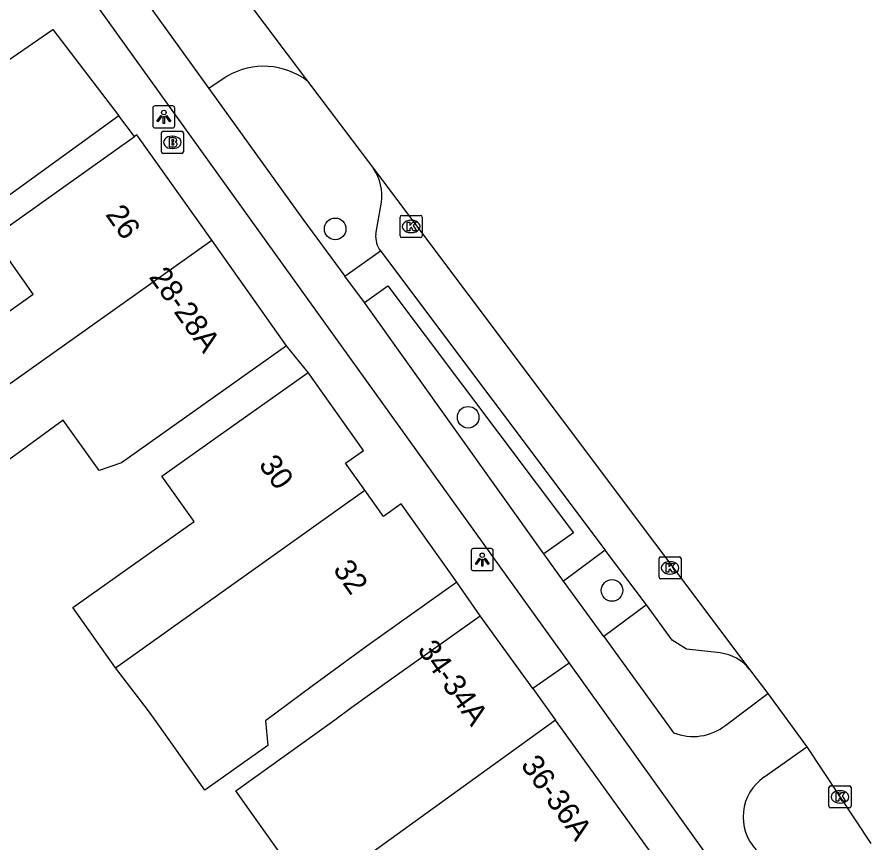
# Model space of a CAD drawing. Extents: x 161845 to 162341, y 381620 to 382158.
# Drawn here: x 162004.73 to 162043.44, y 382005.06 to 382042.47 of the extents above; entities that cross this region are included whole.
import ezdxf

# ---------------------------------------------------------------- set-up
doc = ezdxf.new("R2010")
doc.units = 0
for name, color, linetype in [('IMGEO_Boom', 7, 'Continuous'), ('IMGEO_Brandkraan', 7, 'Continuous'), ('IMGEO_Kolk', 7, 'Continuous'), ('IMGEO_Lichtpunt', 7, 'Continuous'), ('IMGEO_Pand', 7, 'Continuous'), ('IMGEO_Pand_nummerreeks', 7, 'Continuous'), ('IMGEO_Parkeervlak_open', 7, 'Continuous'), ('IMGEO_Rijbaan_lokaal_gesloten', 7, 'Continuous'), ('IMGEO_Rijbaan_lokaal_open', 7, 'Continuous'), ('IMGEO_Verkeerseiland_groen', 7, 'Continuous'), ('IMGEO_Voetpad_open', 7, 'Continuous')]:
    doc.layers.add(name, color=color, linetype=linetype)

msp = doc.modelspace()

# ---------------------------------------------------------------- linework, layer by layer
at = {"layer": 'IMGEO_Boom'}
for centre in [(162019.153, 382032.878), (162025.181, 382024.342), (162031.701, 382016.495)]:
    msp.add_circle(centre, 0.489, dxfattribs=at)
at = {"layer": 'IMGEO_Brandkraan'}
for p, q in [((162011.274, 382036.372), (162011.274, 382037.224)), ((162011.349, 382037.298), (162012.201, 382037.298)), ((162011.762, 382037.078), (162011.787, 382037.078)), ((162012.275, 382037.224), (162012.275, 382036.372)), ((162012.201, 382036.298), (162011.349, 382036.298)), ((162011.785, 382036.518), (162011.76, 382036.518))]:
    msp.add_line(p, q, dxfattribs=at)
for points in [[(162011.274, 382036.372), (162011.274, 382037.224)], [(162011.349, 382037.298), (162012.201, 382037.298)], [(162012.275, 382037.224), (162012.275, 382036.372)], [(162011.622, 382036.998), (162011.622, 382036.598), (162011.835, 382036.598)], [(162011.853, 382036.998), (162011.622, 382036.998)], [(162011.801, 382036.917), (162011.747, 382036.917), (162011.747, 382036.841)], [(162011.747, 382036.841), (162011.8, 382036.841)], [(162011.809, 382036.765), (162011.747, 382036.765), (162011.747, 382036.684)], [(162011.747, 382036.684), (162011.809, 382036.684)], [(162012.201, 382036.298), (162011.349, 382036.298)]]:
    msp.add_lwpolyline(points, dxfattribs=at)
for centre, radius, start, end in [((162011.351, 382037.222), 0.0765, 91.552, 178.448), ((162011.351, 382037.222), 0.0765, 91.552, 178.448), ((162012.199, 382037.222), 0.0765, 1.552, 88.448), ((162012.199, 382037.222), 0.0765, 1.552, 88.448), ((162011.802, 382036.879), 0.0379, 267.8285, 90.9355), ((162011.81, 382036.724), 0.0404, 269.8759, 90.5077), ((162011.857, 382036.853), 0.145, 59.4692, 91.5367), ((162011.882, 382036.9), 0.0922, 285.5137, 58.1501), ((162011.887, 382036.708), 0.105, 301.3115, 78.989), ((162011.351, 382036.374), 0.0765, 181.552, 268.448), ((162011.351, 382036.374), 0.0765, 181.552, 268.448), ((162011.841, 382036.849), 0.251, 268.6676, 293.5347), ((162012.199, 382036.374), 0.0765, 271.552, 358.448), ((162012.199, 382036.374), 0.0765, 271.552, 358.448)]:
    msp.add_arc(centre, radius, start, end, dxfattribs=at)
for centre, major_axis, ratio, start_param, end_param in [((162011.761, 382036.798), (-0.387, 0.002), 0.722429, 4.712389, 7.853982), ((162011.786, 382036.798), (-0.39, 0.002), 0.717154, 1.570796, 4.712389)]:
    msp.add_ellipse(centre, major_axis=major_axis, ratio=ratio, start_param=start_param, end_param=end_param, dxfattribs=at)
at = {"layer": 'IMGEO_Kolk'}
for p, q in [((162022.097, 382032.56), (162022.097, 382033.412)), ((162022.172, 382033.486), (162023.024, 382033.486)), ((162022.585, 382033.266), (162022.61, 382033.266)), ((162023.098, 382033.412), (162023.098, 382032.56)), ((162023.024, 382032.486), (162022.172, 382032.486)), ((162022.608, 382032.706), (162022.583, 382032.706)), ((162033.832, 382017.09), (162033.832, 382017.942)), ((162033.907, 382018.016), (162034.759, 382018.016)), ((162034.32, 382017.796), (162034.345, 382017.796)), ((162034.833, 382017.942), (162034.833, 382017.09)), ((162034.759, 382017.016), (162033.907, 382017.016)), ((162034.343, 382017.236), (162034.318, 382017.236)), ((162041.611, 382007.64), (162042.463, 382007.64)), ((162041.536, 382006.714), (162041.536, 382007.566)), ((162042.024, 382007.42), (162042.049, 382007.42)), ((162042.537, 382007.566), (162042.537, 382006.714)), ((162042.047, 382006.86), (162042.022, 382006.86)), ((162042.463, 382006.64), (162041.611, 382006.64))]:
    msp.add_line(p, q, dxfattribs=at)
for points in [[(162022.097, 382032.56), (162022.097, 382033.412)], [(162022.172, 382033.486), (162023.024, 382033.486)], [(162022.418, 382033.186), (162022.541, 382033.186), (162022.541, 382033.035), (162022.671, 382033.186), (162022.835, 382033.186), (162022.689, 382033.035), (162022.842, 382032.786), (162022.69, 382032.786), (162022.605, 382032.95), (162022.541, 382032.883), (162022.541, 382032.786), (162022.418, 382032.786), (162022.418, 382033.186)], [(162023.098, 382033.412), (162023.098, 382032.56)], [(162023.024, 382032.486), (162022.172, 382032.486)], [(162033.832, 382017.09), (162033.832, 382017.942)], [(162033.907, 382018.016), (162034.759, 382018.016)], [(162034.153, 382017.716), (162034.276, 382017.716), (162034.276, 382017.565), (162034.406, 382017.716), (162034.57, 382017.716), (162034.424, 382017.565), (162034.577, 382017.316), (162034.425, 382017.316), (162034.34, 382017.48), (162034.276, 382017.413), (162034.276, 382017.316), (162034.153, 382017.316), (162034.153, 382017.716)], [(162034.833, 382017.942), (162034.833, 382017.09)], [(162034.759, 382017.016), (162033.907, 382017.016)], [(162041.611, 382007.64), (162042.463, 382007.64)], [(162041.536, 382006.714), (162041.536, 382007.566)], [(162041.857, 382007.34), (162041.98, 382007.34), (162041.98, 382007.189), (162042.11, 382007.34), (162042.274, 382007.34), (162042.128, 382007.189), (162042.281, 382006.94), (162042.129, 382006.94), (162042.044, 382007.104), (162041.98, 382007.037), (162041.98, 382006.94), (162041.857, 382006.94), (162041.857, 382007.34)], [(162042.537, 382007.566), (162042.537, 382006.714)], [(162042.463, 382006.64), (162041.611, 382006.64)]]:
    msp.add_lwpolyline(points, dxfattribs=at)
for centre, start, end in [((162022.174, 382033.41), 91.552, 178.448), ((162022.174, 382033.41), 91.552, 178.448), ((162023.022, 382033.41), 1.552, 88.448), ((162023.022, 382033.41), 1.552, 88.448), ((162022.174, 382032.562), 181.552, 268.448), ((162022.174, 382032.562), 181.552, 268.448), ((162023.022, 382032.562), 271.552, 358.448), ((162023.022, 382032.562), 271.552, 358.448), ((162033.909, 382017.94), 91.552, 178.448), ((162033.909, 382017.94), 91.552, 178.448), ((162034.757, 382017.94), 1.552, 88.448), ((162034.757, 382017.94), 1.552, 88.448), ((162033.909, 382017.092), 181.552, 268.448), ((162033.909, 382017.092), 181.552, 268.448), ((162034.757, 382017.092), 271.552, 358.448), ((162034.757, 382017.092), 271.552, 358.448), ((162041.613, 382007.564), 91.552, 178.448), ((162041.613, 382007.564), 91.552, 178.448), ((162042.461, 382007.564), 1.552, 88.448), ((162042.461, 382007.564), 1.552, 88.448), ((162041.613, 382006.716), 181.552, 268.448), ((162041.613, 382006.716), 181.552, 268.448), ((162042.461, 382006.716), 271.552, 358.448), ((162042.461, 382006.716), 271.552, 358.448)]:
    msp.add_arc(centre, 0.0765, start, end, dxfattribs=at)
for centre, major_axis, ratio, start_param, end_param in [((162022.584, 382032.986), (-0.387, 0.002), 0.722429, 4.712389, 7.853982), ((162022.609, 382032.986), (-0.39, 0.002), 0.717154, 1.570796, 4.712389), ((162034.319, 382017.516), (-0.387, 0.002), 0.722429, 4.712389, 7.853982), ((162034.344, 382017.516), (-0.39, 0.002), 0.717154, 1.570796, 4.712389), ((162042.023, 382007.14), (-0.387, 0.002), 0.722429, 4.712389, 7.853982), ((162042.048, 382007.14), (-0.39, 0.002), 0.717154, 1.570796, 4.712389)]:
    msp.add_ellipse(centre, major_axis=major_axis, ratio=ratio, start_param=start_param, end_param=end_param, dxfattribs=at)
at = {"layer": 'IMGEO_Lichtpunt'}
for p, q in [((162010.887, 382038.353), (162010.887, 382037.546)), ((162010.887, 382038.353), (162010.887, 382037.546)), ((162011.789, 382038.448), (162010.981, 382038.448)), ((162011.789, 382038.448), (162010.981, 382038.448)), ((162011.883, 382037.546), (162011.883, 382038.353)), ((162011.883, 382037.546), (162011.883, 382038.353)), ((162010.981, 382037.452), (162011.789, 382037.452)), ((162010.981, 382037.452), (162011.789, 382037.452)), ((162025.321, 382018.294), (162025.321, 382017.487)), ((162025.321, 382018.294), (162025.321, 382017.487)), ((162026.223, 382018.389), (162025.415, 382018.389)), ((162026.223, 382018.389), (162025.415, 382018.389)), ((162026.317, 382017.487), (162026.317, 382018.294)), ((162026.317, 382017.487), (162026.317, 382018.294)), ((162025.415, 382017.393), (162026.223, 382017.393)), ((162025.415, 382017.393), (162026.223, 382017.393))]:
    msp.add_line(p, q, dxfattribs=at)
for points in [[(162011.261, 382038.017), (162011.3, 382037.989), (162011.112, 382037.727), (162011.074, 382037.754), (162011.261, 382038.017)], [(162011.363, 382037.969), (162011.41, 382037.969), (162011.41, 382037.647), (162011.363, 382037.647), (162011.363, 382037.969)], [(162011.473, 382037.989), (162011.511, 382038.016), (162011.698, 382037.754), (162011.659, 382037.726), (162011.473, 382037.989)], [(162025.695, 382017.958), (162025.734, 382017.93), (162025.546, 382017.668), (162025.508, 382017.695), (162025.695, 382017.958)], [(162025.797, 382017.91), (162025.844, 382017.91), (162025.844, 382017.588), (162025.797, 382017.588), (162025.797, 382017.91)], [(162025.907, 382017.93), (162025.945, 382017.957), (162026.132, 382017.695), (162026.093, 382017.667), (162025.907, 382017.93)]]:
    msp.add_lwpolyline(points, dxfattribs=at)
for centre in [(162011.386, 382038.151), (162025.82, 382018.092)]:
    msp.add_circle(centre, 0.0994, dxfattribs=at)
for centre, start, end in [((162010.981, 382038.353), 90, 180), ((162010.981, 382038.353), 90, 180), ((162011.789, 382038.353), 0, 90), ((162011.789, 382038.353), 0, 90), ((162010.981, 382037.546), 180, 270), ((162010.981, 382037.546), 180, 270), ((162011.789, 382037.546), 270, 0), ((162011.789, 382037.546), 270, 360), ((162025.415, 382018.294), 90, 180), ((162025.415, 382018.294), 90, 180), ((162026.223, 382018.294), 0, 90), ((162026.223, 382018.294), 0, 90), ((162025.415, 382017.487), 180, 270), ((162025.415, 382017.487), 180, 270), ((162026.223, 382017.487), 270, 0), ((162026.223, 382017.487), 270, 360)]:
    msp.add_arc(centre, 0.0946, start, end, dxfattribs=at)
at = {"layer": 'IMGEO_Pand'}
for points in [[(161997.249, 382029.239), (161999.706, 382025.835), (162001.629, 382027.199), (162002.391, 382027.74), (162005.47, 382029.923), (162003.635, 382032.508), (162010.053, 382037.06)], [(162013.56, 382032.36), (162010.168, 382037.142), (162010.053, 382037.06)], [(161998.103, 382021.397), (162013.56, 382032.36)], [(162016.951, 382027.58), (162013.56, 382032.36)], [(162016.951, 382027.58), (162009.474, 382022.275), (162008.449, 382021.931), (162006.82, 382024.205), (162004.8, 382022.73), (162004.095, 382022.215), (161999.767, 382019.055)], [(162009.198, 382012.996), (162007.268, 382015.716), (162012.762, 382019.613), (162011.3, 382021.673), (162013.848, 382023.481), (162017.926, 382026.373)], [(162020.497, 382021.037), (162019.623, 382022.269), (162020.431, 382022.842), (162017.926, 382026.373)], [(162009.198, 382012.996), (162020.497, 382021.037)], [(162024.672, 382016.864), (162022.15, 382020.419), (162021.343, 382019.845), (162020.497, 382021.037)], [(162024.672, 382016.864), (162020.594, 382013.971), (162018.111, 382012.155), (162015.992, 382010.589), (162016.098, 382009.464), (162013.245, 382007.44), (162011.109, 382010.45), (162010.694, 382011.035), (162009.198, 382012.996)], [(162018.054, 382002.618), (162016.389, 382004.966), (162014.656, 382007.41), (162019.136, 382010.639), (162019.915, 382011.201), (162021.722, 382012.503), (162025.731, 382015.347)], [(162028.111, 382012.05), (162025.731, 382015.347)], [(162028.111, 382012.05), (162029.147, 382010.614)], [(162029.147, 382010.614), (162018.054, 382002.618)], [(162033.436, 382004.671), (162029.388, 382010.279), (162029.147, 382010.614)]]:
    msp.add_lwpolyline(points, dxfattribs=at)
at = {"layer": 'IMGEO_Parkeervlak_open'}
for points in [[(162020.995, 382032.644), (162021.253, 382034.081)], [(162033.266, 382015.843), (162031.39, 382018.316)], [(162036.602, 382013.663), (162035.083, 382013.841), (162034.436, 382014.235), (162033.266, 382015.843)]]:
    msp.add_lwpolyline(points, dxfattribs=at)
for centre, radius, start, end in [((162019.157, 382034.382), 2.117, 351.8164, 35.4075), ((162022.038, 382032.525), 1.05, 173.4762, 217.7581), ((162036.382, 382011.703), 1.972, 37.5503, 83.6047)]:
    msp.add_arc(centre, radius, start, end, dxfattribs=at)
at = {"layer": 'IMGEO_Rijbaan_lokaal_gesloten'}
for points in [[(162010.029, 382050.037), (162017.899, 382039.578)], [(162017.899, 382039.578), (162017.902, 382039.574), (162020.883, 382035.609)], [(162020.883, 382035.609), (162037.946, 382012.905)], [(162037.946, 382012.905), (162038.772, 382011.821)], [(162038.772, 382011.821), (162040.532, 382009.408)], [(162040.532, 382009.408), (162043.438, 382005.028)]]:
    msp.add_lwpolyline(points, dxfattribs=at)
at = {"layer": 'IMGEO_Rijbaan_lokaal_open'}
for points in [[(162000.906, 382038.161), (162006.35, 382041.909), (162009.342, 382037.993)], [(162009.342, 382037.993), (162000, 382031.23), (161997.249, 382029.239)]]:
    msp.add_lwpolyline(points, dxfattribs=at)
at = {"layer": 'IMGEO_Verkeerseiland_groen'}
msp.add_lwpolyline([(162033.266, 382015.843), (162031.325, 382014.409)], dxfattribs=at)
at = {"layer": 'IMGEO_Voetpad_open'}
for points in [[(161987.189, 382070.102), (162005.618, 382046.645), (162008.125, 382043.316), (162027.362, 382016.531), (162029.757, 382013.196)], [(162007.95, 382046.834), (162013.424, 382039.241)], [(162014.261, 382039.8), (162013.424, 382039.241)], [(162013.424, 382039.241), (162017.69, 382033.323), (162019.585, 382030.742)], [(162010.053, 382037.06), (162009.342, 382037.993)], [(162019.585, 382030.742), (162021.208, 382031.882)], [(162021.208, 382031.882), (162031.39, 382018.316)], [(162020.481, 382029.536), (162019.585, 382030.742)], [(162020.481, 382029.536), (162021.546, 382030.301), (162029.959, 382019.109), (162028.609, 382018.147)], [(162028.609, 382018.147), (162020.481, 382029.536)], [(162017.926, 382026.373), (162016.951, 382027.58)], [(162029.506, 382016.916), (162028.609, 382018.147)], [(162031.39, 382018.316), (162029.506, 382016.916)], [(162031.325, 382014.409), (162029.506, 382016.916)], [(162025.731, 382015.347), (162024.672, 382016.864)], [(162031.325, 382014.409), (162034.261, 382010.362), (162034.488, 382010.049)], [(162029.757, 382013.196), (162028.111, 382012.05)], [(162029.757, 382013.196), (162035.937, 382004.58)], [(162036.859, 382010.393), (162038.772, 382011.821)], [(162038.588, 382008.032), (162040.532, 382009.408)]]:
    msp.add_lwpolyline(points, dxfattribs=at)
for centre, radius, start, end in [((162015.913, 382036.948), 3.296, 52.9427, 120.0733), ((162035.379, 382012.251), 2.375, 247.9653, 308.5451), ((162039.833, 382006.234), 2.187, 124.6892, 223.108)]:
    msp.add_arc(centre, radius, start, end, dxfattribs=at)

# ---------------------------------------------------------------- texts
at = {"layer": 'IMGEO_Pand_nummerreeks'}
for s, rotation, p in [('26', 305.3513, (162008.711, 382033.527)), ('28-28A', 305.632, (162010.684, 382030.696)), ('30', 305.3584, (162015.656, 382022.191)), ('32', 305.357, (162019.026, 382017.442)), ('34-34A', 305.1966, (162022.853, 382013.805)), ('36-36A', 305.8154, (162027.534, 382008.578))]:
    msp.add_text(s, height=1, rotation=rotation, dxfattribs=at).set_placement(p)

doc.saveas('drawing.dxf')
